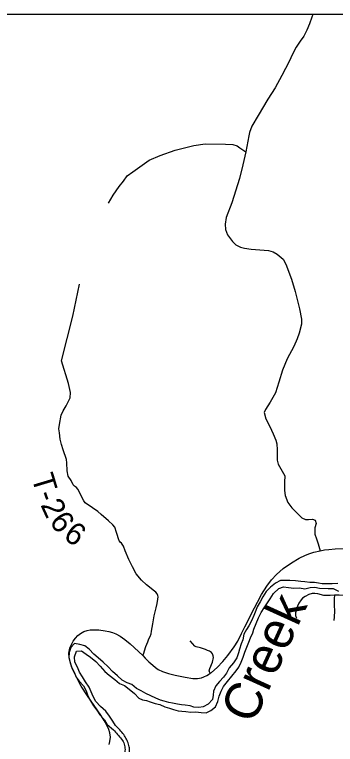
# Model space of a CAD drawing. Extents: x -10.5 to 40.6, y -3.2 to 22.
# Drawn here: x -6.111 to -5.292, y 19.035 to 20.9 of the extents above; entities that cross this region are included whole.
import ezdxf

# ---------------------------------------------------------------- set-up
doc = ezdxf.new("R2010")
doc.units = 0
for name, color, linetype in [('GM_X_County_Road', 7, 'Continuous'), ('GM_X_Major_River', 7, 'Continuous'), ('GM_X_Major_River_Text', 7, 'Continuous'), ('GM_X_State_Route', 7, 'Continuous'), ('GM_X_Township_Road', 7, 'Continuous'), ('GM_X_Township_Road_Text', 7, 'Continuous'), ('GM_X_Township_Text', 7, 'Continuous')]:
    doc.layers.add(name, color=color, linetype=linetype)

msp = doc.modelspace()

# ---------------------------------------------------------------- linework, layer by layer
at = {"layer": 'GM_X_County_Road'}
msp.add_lwpolyline([(-5.3497, 20.9), (-5.3517, 20.8938), (-5.3576, 20.8767), (-5.3648, 20.8601), (-5.3727, 20.8452), (-5.3814, 20.8323), (-5.3921, 20.8169), (-5.4015, 20.7988), (-5.4102, 20.7802), (-5.4288, 20.744), (-5.4461, 20.713), (-5.4642, 20.6843), (-5.4895, 20.6419), (-5.5049, 20.6146), (-5.5116, 20.5987), (-5.5133, 20.5905), (-5.521, 20.5491), (-5.5282, 20.5164), (-5.5366, 20.4814), (-5.5562, 20.419), (-5.5708, 20.3818), (-5.5738, 20.3647), (-5.5723, 20.3513), (-5.5671, 20.3374), (-5.555, 20.3205), (-5.5458, 20.3113), (-5.5342, 20.3056), (-5.5242, 20.3032), (-5.5069, 20.3009), (-5.4627, 20.297), (-5.4511, 20.2935), (-5.4402, 20.2878), (-5.4255, 20.2749), (-5.4184, 20.262), (-5.4037, 20.2238), (-5.3948, 20.1926), (-5.3831, 20.1479), (-5.3787, 20.1222), (-5.3787, 20.1088), (-5.3841, 20.0857), (-5.3891, 20.0718), (-5.398, 20.052), (-5.4151, 20.0207), (-5.4273, 19.9917), (-5.436, 19.9607), (-5.4451, 19.9339), (-5.4584, 19.9101), (-5.4707, 19.8913), (-5.4737, 19.8831), (-5.4692, 19.8675), (-5.4593, 19.8474), (-5.4506, 19.8291), (-5.4439, 19.8127), (-5.4414, 19.8033), (-5.4407, 19.7881), (-5.4402, 19.7616), (-5.4377, 19.7515), (-5.4313, 19.7393), (-5.4211, 19.7217), (-5.4216, 19.7053), (-5.4221, 19.684), (-5.4201, 19.6711), (-5.4136, 19.6533), (-5.403, 19.6396), (-5.3913, 19.6277), (-5.3772, 19.6141), (-5.3685, 19.6096), (-5.3606, 19.6096), (-5.3507, 19.6109), (-5.3435, 19.6081), (-5.3412, 19.5999), (-5.3447, 19.5888), (-5.3442, 19.572), (-5.3405, 19.5604), (-5.3361, 19.548), (-5.331, 19.5295)], dxfattribs=at)
at = {"layer": 'GM_X_Major_River'}
for points in [[(-5.286, 19.4462), (-5.3, 19.4456), (-5.3129, 19.4451), (-5.3254, 19.4457), (-5.3353, 19.4475), (-5.3451, 19.4486), (-5.3572, 19.4492), (-5.3697, 19.451), (-5.3803, 19.4512), (-5.394, 19.4534), (-5.408, 19.454), (-5.4201, 19.4542), (-5.4322, 19.4537), (-5.4446, 19.4468), (-5.4577, 19.4368), (-5.4686, 19.4256), (-5.4772, 19.4119), (-5.4842, 19.3993), (-5.4913, 19.3871), (-5.4953, 19.3772), (-5.5001, 19.3646), (-5.5064, 19.3513), (-5.5131, 19.3383), (-5.519, 19.3288), (-5.5253, 19.3166), (-5.5286, 19.3021), (-5.5322, 19.2926), (-5.537, 19.2785), (-5.5392, 19.269), (-5.5432, 19.2568), (-5.5521, 19.2439), (-5.563, 19.2305), (-5.5704, 19.2175), (-5.5775, 19.2072), (-5.5876, 19.1957), (-5.5969, 19.1846), (-5.6036, 19.1713), (-5.6042, 19.1614)], [(-5.5388, 19.233), (-5.5325, 19.2452), (-5.5273, 19.2585), (-5.5229, 19.2707), (-5.5178, 19.284), (-5.513, 19.2966), (-5.5086, 19.3077), (-5.503, 19.3206), (-5.5001, 19.3301), (-5.4938, 19.3442), (-5.4879, 19.3587), (-5.4813, 19.3724), (-5.4734, 19.3843), (-5.4656, 19.3972), (-5.4586, 19.4075), (-5.4496, 19.4205), (-5.4365, 19.4336), (-5.4248, 19.4375), (-5.4116, 19.4365), (-5.3983, 19.4347), (-5.3836, 19.4353), (-5.3703, 19.4328), (-5.3567, 19.4363), (-5.3442, 19.4368), (-5.3321, 19.4347), (-5.3101, 19.4334), (-5.2973, 19.4332), (-5.2839, 19.4272)], [(-5.6042, 19.1614), (-5.6056, 19.1496), (-5.6165, 19.1381), (-5.6296, 19.1312), (-5.641, 19.1299), (-5.6531, 19.1301), (-5.663, 19.1335), (-5.6755, 19.1352), (-5.6849, 19.1366), (-5.6948, 19.1377), (-5.7077, 19.1406), (-5.7172, 19.1424), (-5.7289, 19.146), (-5.7384, 19.1482), (-5.7506, 19.1534), (-5.7635, 19.1593), (-5.7757, 19.1653), (-5.7879, 19.1723), (-5.8, 19.1779), (-5.8115, 19.1884), (-5.8237, 19.1924), (-5.8362, 19.1995), (-5.8485, 19.2104), (-5.8614, 19.2212), (-5.8722, 19.2333), (-5.8848, 19.2453), (-5.8974, 19.2561), (-5.9089, 19.2659), (-5.9211, 19.2782), (-5.9322, 19.2868), (-5.9447, 19.2909), (-5.958, 19.293), (-5.9677, 19.2827), (-5.9717, 19.2697), (-5.9727, 19.2576), (-5.9696, 19.2447), (-5.966, 19.2326), (-5.9591, 19.2198), (-5.954, 19.2074), (-5.9467, 19.1964), (-5.9352, 19.1848), (-5.9286, 19.172), (-5.924, 19.1595), (-5.9174, 19.1467), (-5.9097, 19.1342), (-5.9012, 19.123), (-5.8935, 19.1109), (-5.882, 19.0978), (-5.8744, 19.0857), (-5.8589, 19.0727)], [(-5.8426, 19.0722), (-5.8534, 19.0837), (-5.8601, 19.095), (-5.8685, 19.107), (-5.8785, 19.1198), (-5.8915, 19.1318), (-5.9034, 19.1449), (-5.9103, 19.1574), (-5.9158, 19.1698), (-5.9208, 19.1819), (-5.93, 19.1951), (-5.9377, 19.2079), (-5.9451, 19.22), (-5.9505, 19.2328), (-5.9574, 19.2452), (-5.958, 19.2593), (-5.9528, 19.2734), (-5.9404, 19.2746), (-5.9285, 19.2656), (-5.9171, 19.2582), (-5.9034, 19.2473), (-5.8926, 19.2349), (-5.8811, 19.2218), (-5.8693, 19.212), (-5.8552, 19.2008), (-5.843, 19.1911), (-5.8308, 19.1855), (-5.8186, 19.1766), (-5.8052, 19.1653), (-5.7937, 19.1533), (-5.7842, 19.1492), (-5.7744, 19.1471), (-5.7649, 19.1441), (-5.7523, 19.1401), (-5.7406, 19.1368), (-5.7276, 19.1312), (-5.7159, 19.128), (-5.7056, 19.1243), (-5.6935, 19.1214), (-5.684, 19.12), (-5.6738, 19.1189), (-5.6613, 19.1179), (-5.6484, 19.1181), (-5.6351, 19.1171), (-5.6223, 19.1157), (-5.6102, 19.1215), (-5.5978, 19.1315), (-5.5923, 19.1448), (-5.5883, 19.1585), (-5.5835, 19.1711), (-5.5776, 19.1833), (-5.5675, 19.1963), (-5.5451, 19.2231), (-5.5388, 19.233)]]:
    msp.add_lwpolyline(points, dxfattribs=at)
for points in [[(-5.8589, 19.0727), (-5.8485, 19.0607), (-5.838, 19.0484), (-5.8313, 19.0356), (-5.8292, 19.0219), (-5.8305, 19.0098), (-5.8341, 18.9972), (-5.8411, 18.9845), (-5.8511, 18.9714), (-5.863, 18.9602), (-5.8761, 18.9474), (-5.8891, 18.9358), (-5.8989, 18.9273), (-5.9104, 18.9168), (-5.922, 18.9052), (-5.934, 18.8952), (-5.9471, 18.887), (-5.9602, 18.8784), (-5.9734, 18.8706), (-5.9858, 18.865), (-5.9982, 18.8599), (-6.0111, 18.8577), (-6.0258, 18.8529), (-6.0386, 18.85), (-6.0503, 18.8479), (-6.0628, 18.8458), (-6.0757, 18.8426), (-6.0873, 18.8374), (-6.1008, 18.8285), (-6.1113, 18.8176), (-6.1236, 18.8053), (-6.1363, 18.7948), (-6.1493, 18.7824), (-6.1613, 18.7739), (-6.1746, 18.7729), (-6.1872, 18.7761), (-6.2009, 18.7781), (-6.2138, 18.7832), (-6.2265, 18.7906), (-6.2391, 18.7961), (-6.2518, 18.8042), (-6.2633, 18.8112), (-6.2755, 18.8163), (-6.2888, 18.818), (-6.2983, 18.8182), (-6.3116, 18.8203), (-6.326, 18.8219), (-6.3405, 18.8247), (-6.3535, 18.829), (-6.3653, 18.8307), (-6.3774, 18.832), (-6.3891, 18.8295), (-6.3989, 18.8248), (-6.4102, 18.8193), (-6.4218, 18.8092), (-6.4303, 18.7973), (-6.4381, 18.7877), (-6.4466, 18.7739), (-6.4517, 18.7605), (-6.4568, 18.7501), (-6.46, 18.7379), (-6.4594, 18.7243), (-6.4565, 18.7118), (-6.4525, 18.6993), (-6.4504, 18.688), (-6.4479, 18.6739), (-6.4458, 18.6603), (-6.441, 18.6471), (-6.4347, 18.6343), (-6.4291, 18.6211), (-6.4247, 18.6083), (-6.4204, 18.5962), (-6.416, 18.5833), (-6.4154, 18.5712), (-6.411, 18.5587), (-6.4058, 18.5467), (-6.3992, 18.5343), (-6.394, 18.5222), (-6.3836, 18.5098), (-6.3712, 18.4987), (-6.3631, 18.4867), (-6.3526, 18.4728), (-6.3482, 18.4603), (-6.3461, 18.4486), (-6.3425, 18.4373), (-6.3434, 18.4232), (-6.3477, 18.4102), (-6.3536, 18.3976), (-6.3632, 18.3856), (-6.3752, 18.3759), (-6.3879, 18.367), (-6.4011, 18.3595), (-6.4135, 18.3525), (-6.4281, 18.3465), (-6.4413, 18.3406), (-6.456, 18.3331), (-6.4692, 18.3291)], [(-6.4358, 18.3297), (-6.423, 18.3352), (-6.4113, 18.3396), (-6.4012, 18.3447), (-6.3895, 18.3502), (-6.376, 18.3569), (-6.3636, 18.3624), (-6.3512, 18.3741), (-6.3427, 18.386), (-6.3346, 18.3987), (-6.3292, 18.4139), (-6.3267, 18.4261), (-6.3254, 18.4387), (-6.3268, 18.4489), (-6.3312, 18.4625), (-6.3374, 18.4738), (-6.3448, 18.4858), (-6.3519, 18.4979), (-6.3619, 18.5072), (-6.3727, 18.5184), (-6.3839, 18.53), (-6.3891, 18.542), (-6.3942, 18.5537), (-6.3978, 18.5662), (-6.4014, 18.5768), (-6.4039, 18.5892), (-6.408, 18.604), (-6.4127, 18.6157), (-6.4183, 18.6289), (-6.4231, 18.6417), (-6.4271, 18.6538), (-6.4303, 18.664), (-6.435, 18.6768), (-6.4371, 18.687), (-6.44, 18.6991), (-6.4417, 18.709), (-6.4434, 18.7211), (-6.4433, 18.7348), (-6.4427, 18.7473), (-6.4388, 18.7596), (-6.4337, 18.7726), (-6.4252, 18.786), (-6.4163, 18.7979), (-6.4051, 18.8084), (-6.3927, 18.8154), (-6.381, 18.8187), (-6.3681, 18.8174), (-6.3562, 18.8134), (-6.3425, 18.8083), (-6.3303, 18.8047), (-6.317, 18.8023), (-6.3067, 18.8017), (-6.2934, 18.8012), (-6.2797, 18.7984), (-6.2695, 18.7971), (-6.2561, 18.7927), (-6.2439, 18.7861), (-6.232, 18.7799), (-6.2205, 18.7728), (-6.2086, 18.7662), (-6.1949, 18.7611), (-6.1812, 18.7572), (-6.1679, 18.7593), (-6.1539, 18.7634), (-6.1407, 18.7678), (-6.1276, 18.7775), (-6.1172, 18.7902), (-6.1065, 18.8037), (-6.0968, 18.8168), (-6.083, 18.8254), (-6.058, 18.8288), (-6.0425, 18.834), (-6.0293, 18.8377), (-6.0157, 18.8421), (-6.0056, 18.8464), (-5.9916, 18.8501), (-5.9814, 18.8533), (-5.9682, 18.8589), (-5.9554, 18.8655), (-5.9431, 18.8734), (-5.9292, 18.882), (-5.9168, 18.8913), (-5.9083, 18.9009), (-5.8952, 18.9125), (-5.8828, 18.9226), (-5.8694, 18.9354), (-5.8571, 18.947), (-5.8455, 18.959), (-5.8355, 18.9717), (-5.8282, 18.9851), (-5.8216, 18.9981), (-5.818, 19.01), (-5.8175, 19.0229), (-5.82, 19.0358), (-5.8255, 19.0486), (-5.8325, 19.0602), (-5.8426, 19.0722)]]:
    msp.add_spline(points, degree=3, dxfattribs=at)
at = {"layer": 'GM_X_State_Route'}
msp.add_lwpolyline([(-5.8697, 19.0351), (-5.8677, 19.0427), (-5.8667, 19.0537), (-5.8682, 19.0645), (-5.8708, 19.0734), (-5.8748, 19.0826), (-5.8828, 19.0966), (-5.891, 19.11), (-5.9251, 19.1597), (-5.9409, 19.1842), (-5.9508, 19.202), (-5.9567, 19.214), (-5.9638, 19.2304), (-5.9682, 19.243), (-5.9719, 19.2562), (-5.9727, 19.2683), (-5.9703, 19.2813), (-5.9652, 19.2925), (-5.9617, 19.2987), (-5.9558, 19.3068), (-5.9496, 19.3134), (-5.943, 19.3188), (-5.9345, 19.3238), (-5.9261, 19.3263), (-5.9186, 19.3276), (-5.9084, 19.3282), (-5.8965, 19.3278), (-5.8798, 19.3258), (-5.8703, 19.3238), (-5.8608, 19.3213), (-5.8524, 19.3178), (-5.8419, 19.3119), (-5.8299, 19.3033), (-5.816, 19.2918), (-5.784, 19.2621), (-5.7776, 19.2553), (-5.7687, 19.2465), (-5.7585, 19.2373), (-5.7512, 19.2316), (-5.7442, 19.227), (-5.7336, 19.2219), (-5.7181, 19.2165), (-5.7007, 19.2123), (-5.6757, 19.207), (-5.656, 19.204), (-5.6441, 19.204), (-5.634, 19.2054), (-5.6275, 19.2079), (-5.6205, 19.211), (-5.6157, 19.2137), (-5.6114, 19.217), (-5.6084, 19.2191), (-5.5937, 19.232), (-5.5795, 19.247), (-5.5665, 19.2626), (-5.5504, 19.2843), (-5.5413, 19.2991), (-5.5313, 19.3185), (-5.523, 19.3353), (-5.4981, 19.3846), (-5.4912, 19.3988), (-5.481, 19.418), (-5.4672, 19.4395), (-5.455, 19.4558), (-5.4422, 19.4691), (-5.4249, 19.4844), (-5.4039, 19.4994), (-5.3845, 19.5112), (-5.3682, 19.5188), (-5.3572, 19.5231), (-5.3466, 19.5263), (-5.331, 19.5295), (-5.3196, 19.5321), (-5.309, 19.5334), (-5.2927, 19.5347), (-5.2623, 19.5358)], dxfattribs=at)
at = {"layer": 'GM_X_Township_Road'}
msp.add_line((-5.536, 20.5597), (-5.521, 20.5491), dxfattribs=at)
for points in [[(-5.8715, 20.4184), (-5.8591, 20.4382), (-5.8442, 20.4605), (-5.8335, 20.4746), (-5.8236, 20.4878), (-5.8095, 20.4985), (-5.7913, 20.5109), (-5.7674, 20.5283), (-5.7392, 20.5399), (-5.7012, 20.5539), (-5.6533, 20.5655), (-5.6244, 20.5696), (-5.5723, 20.5688), (-5.5541, 20.568), (-5.5431, 20.5648), (-5.536, 20.5597)], [(-5.8433, 19.5545), (-5.8438, 19.5553), (-5.851, 19.5768), (-5.8554, 19.5901), (-5.86, 19.5965), (-5.8715, 19.6069), (-5.8901, 19.6228), (-5.8989, 19.63), (-5.9119, 19.6397), (-5.9313, 19.6528), (-5.9346, 19.6576), (-5.9497, 19.6877), (-5.953, 19.6913), (-5.9585, 19.6951), (-5.9617, 19.6983), (-5.9669, 19.7094), (-5.9744, 19.7209), (-5.9767, 19.7344), (-5.9778, 19.7551), (-5.979, 19.7632), (-5.9869, 19.7877), (-5.9918, 19.8012), (-5.9946, 19.8155), (-5.9967, 19.8312), (-5.9981, 19.8415), (-5.9968, 19.8526), (-5.992, 19.8766), (-5.9876, 19.8874), (-5.9792, 19.9006), (-5.9726, 19.9141), (-5.9694, 19.9212), (-5.9683, 19.9342), (-5.9739, 19.9577), (-5.9917, 20.0149), (-5.9625, 20.1294), (-5.9453, 20.2112)], [(-5.784, 19.2621), (-5.7817, 19.2654), (-5.7762, 19.2857), (-5.7713, 19.2977), (-5.7681, 19.3047), (-5.7648, 19.3112), (-5.7626, 19.3174), (-5.7614, 19.3244), (-5.758, 19.3435), (-5.755, 19.3636), (-5.75, 19.3844), (-5.7472, 19.3955), (-5.7452, 19.4064), (-5.7448, 19.4121), (-5.7454, 19.4156), (-5.7471, 19.4197), (-5.7506, 19.424), (-5.7538, 19.4269), (-5.7741, 19.4431), (-5.7868, 19.4552), (-5.8006, 19.4709), (-5.8101, 19.4892), (-5.8196, 19.5079), (-5.8289, 19.5295), (-5.8335, 19.5419), (-5.8379, 19.5491), (-5.8417, 19.5522), (-5.8433, 19.5545)], [(-5.1978, 19.4066), (-5.2061, 19.4076), (-5.2166, 19.4092), (-5.2232, 19.4105), (-5.2478, 19.4145), (-5.2572, 19.4153), (-5.2675, 19.4156), (-5.2823, 19.4165), (-5.2939, 19.4163), (-5.3049, 19.416), (-5.3211, 19.4157), (-5.3365, 19.4196), (-5.3447, 19.421), (-5.3514, 19.4207), (-5.3595, 19.4182), (-5.3693, 19.4132), (-5.3755, 19.4086), (-5.3795, 19.4048), (-5.3852, 19.3962), (-5.3883, 19.3887), (-5.3924, 19.3769), (-5.3935, 19.3711), (-5.3935, 19.3644), (-5.3912, 19.3577)], [(-5.2939, 19.4163), (-5.295, 19.4083), (-5.2946, 19.3909), (-5.2943, 19.3754), (-5.2946, 19.3612), (-5.2957, 19.3518)], [(-5.6114, 19.217), (-5.6136, 19.2209), (-5.6144, 19.2235), (-5.6127, 19.2288), (-5.6057, 19.245), (-5.6034, 19.2575), (-5.6037, 19.2617), (-5.6045, 19.2645), (-5.6056, 19.2669), (-5.6084, 19.2698), (-5.6136, 19.2734), (-5.6182, 19.2753), (-5.6238, 19.2779), (-5.6365, 19.2816), (-5.6473, 19.2843), (-5.651, 19.286), (-5.663, 19.2995)]]:
    msp.add_lwpolyline(points, dxfattribs=at)
at = {"layer": 'GM_X_Township_Text'}
msp.add_lwpolyline([(-3.7445, 16.8499), (-3.7445, 20.9), (-6.1618, 20.9)], dxfattribs=at)

# ---------------------------------------------------------------- texts
at = {"layer": 'GM_X_Major_River_Text'}
msp.add_text('Creek', height=0.09468, rotation=65.5354, dxfattribs=at).set_placement((-5.5021, 19.0837))
at = {"layer": 'GM_X_Township_Road_Text'}
for s, rotation, p in [('T', 286.7366, (-6.0687, 19.718)), ('-', 289.0523, (-6.0557, 19.6749)), ('2', 294.7249, (-6.0458, 19.6472)), ('6', 306.8832, (-6.0244, 19.6041)), ('6', 324.8057, (-5.9896, 19.5627))]:
    msp.add_text(s, height=0.0568, rotation=rotation, dxfattribs=at).set_placement(p)

doc.saveas('drawing.dxf')
